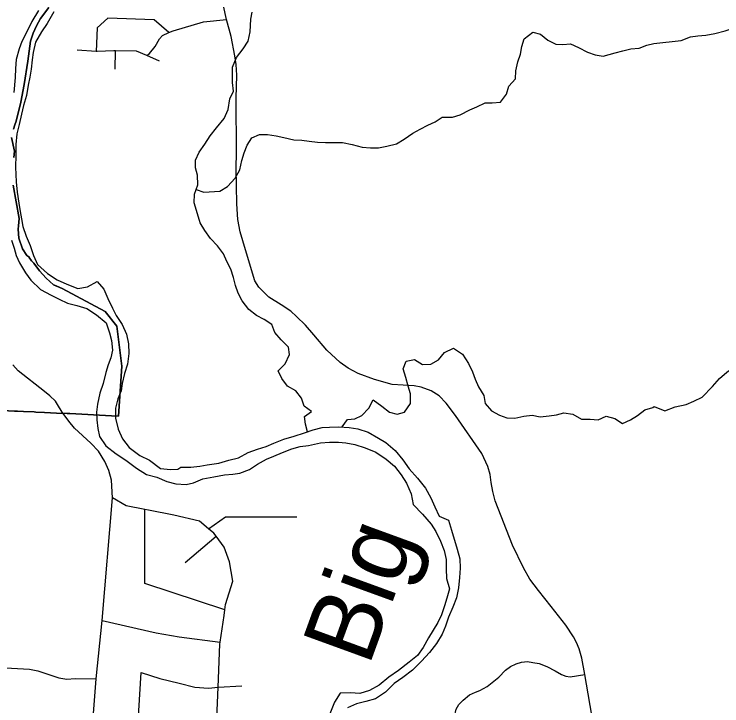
# Model space of a CAD drawing. Extents: x 0 to 34, y 0 to 22.
# Drawn here: x 6.952 to 7.884, y 15.09 to 16 of the extents above; entities that cross this region are included whole.
import ezdxf

# ---------------------------------------------------------------- set-up
doc = ezdxf.new("R2010")
doc.units = 0
for name, color, linetype in [('GM_X_City_Street', 7, 'Continuous'), ('GM_X_Corporation', 7, 'Continuous'), ('GM_X_County_Road', 7, 'Continuous'), ('GM_X_Major_River', 7, 'Continuous'), ('GM_X_Major_River_Text', 7, 'Continuous'), ('GM_X_Minor_Lake', 7, 'Continuous'), ('GM_X_Minor_River', 7, 'Continuous')]:
    doc.layers.add(name, color=color, linetype=linetype)

msp = doc.modelspace()

# ---------------------------------------------------------------- linework, layer by layer
at = {"layer": 'GM_X_City_Street'}
for p, q in [((7.08497, 15.92792), (7.08547, 15.95214)), ((7.17719, 15.27848), (7.2179, 15.31291)), ((7.22068, 15.11423), (7.25195, 15.11592))]:
    msp.add_line(p, q, dxfattribs=at)
for points in [[(7.15596, 15.97631), (7.1365, 15.9931), (7.07538, 15.99512), (7.06123, 15.98249), (7.06015, 15.95124)], [(7.1269, 15.94587), (7.1303, 15.94854), (7.13785, 15.95767), (7.14349, 15.96794), (7.14727, 15.97251), (7.15596, 15.97631), (7.16126, 15.97862), (7.20136, 15.99052), (7.23188, 15.99332)], [(7.14357, 15.93853), (7.1269, 15.94587), (7.11326, 15.95167), (7.08547, 15.95214), (7.08345, 15.95217), (7.06123, 15.95116), (7.06015, 15.95124), (7.03496, 15.95318)], [(7.00904, 15.48646), (7.00648, 15.49066), (6.99904, 15.49765), (6.99197, 15.50353), (6.9571, 15.53091), (6.95032, 15.53886)], [(7.01706, 14.54029), (7.03439, 14.79601), (7.04866, 14.97746), (7.0599, 15.12511), (7.06774, 15.2021), (7.08142, 15.3637), (7.08044, 15.38667), (7.07677, 15.39963), (7.07133, 15.41126), (7.06309, 15.42505), (7.05282, 15.43556), (7.03155, 15.45512), (7.02397, 15.46441), (7.01517, 15.47638), (7.00904, 15.48646)], [(7.21774, 15.0422), (7.22068, 15.11423), (7.22299, 15.17085), (7.2234, 15.17362), (7.22854, 15.20845), (7.22949, 15.21606), (7.23039, 15.22325), (7.24013, 15.25364), (7.23588, 15.27943), (7.22862, 15.29838), (7.2179, 15.31291), (7.21493, 15.31693), (7.20818, 15.3227), (7.19632, 15.33281), (7.16221, 15.34067), (7.12886, 15.34738), (7.12434, 15.34825), (7.09968, 15.35298), (7.08142, 15.3637)], [(7.22949, 15.21606), (7.12426, 15.2506), (7.12434, 15.34825)], [(7.20818, 15.3227), (7.23038, 15.33861), (7.3243, 15.33854)], [(7.06774, 15.2021), (7.13887, 15.18576), (7.16918, 15.18055), (7.2234, 15.17362)], [(7.5378, 15.09161), (7.54324, 15.09715), (7.552, 15.104), (7.55986, 15.10763), (7.5653, 15.10975), (7.57512, 15.11519), (7.58389, 15.12199), (7.59023, 15.12758), (7.5993, 15.13664), (7.60595, 15.14148), (7.6132, 15.14511), (7.62046, 15.14737), (7.62801, 15.14783), (7.63511, 15.14692), (7.64343, 15.14541), (7.65385, 15.14133), (7.66443, 15.13559), (7.67289, 15.13075), (7.67848, 15.12879), (7.68453, 15.12803), (7.70388, 15.13089)], [(6.90876, 15.14136), (6.97202, 15.13778), (6.98301, 15.13591), (7.01069, 15.12652), (7.02129, 15.12465), (7.03227, 15.12583), (7.0599, 15.12511)], [(7.10966, 14.97517), (7.11934, 15.13371), (7.14399, 15.12582), (7.16938, 15.11945), (7.18985, 15.1142), (7.20803, 15.11275), (7.22068, 15.11423)], [(7.53954, 15.02635), (7.53561, 15.03146), (7.53404, 15.04089), (7.53296, 15.05459), (7.53145, 15.06849), (7.5319, 15.07575), (7.53417, 15.08527), (7.5378, 15.09161)]]:
    msp.add_lwpolyline(points, dxfattribs=at)
at = {"layer": 'GM_X_Corporation'}
for points in [[(6.9976, 16.00898), (6.98676, 15.99463), (6.98135, 15.9852), (6.97689, 15.97529), (6.97341, 15.96499), (6.97023, 15.93838), (6.96527, 15.90778), (6.96076, 15.88449), (6.95451, 15.85959), (6.95296, 15.85476), (6.95112, 15.8492)], [(6.95112, 15.8492), (6.95296, 15.85476), (6.95451, 15.85959), (6.96076, 15.88449), (6.96527, 15.90778), (6.97023, 15.93838), (6.97341, 15.96499), (6.97689, 15.97529), (6.98135, 15.9852), (6.98676, 15.99463), (6.9976, 16.00898)], [(6.9484, 15.83781), (6.95234, 15.81982), (6.9514, 15.81153)], [(6.9514, 15.81153), (6.95234, 15.81982), (6.9484, 15.83781)], [(6.95088, 15.77545), (6.95845, 15.73118), (6.95779, 15.7219), (6.95745, 15.71716), (6.95817, 15.70556), (6.96303, 15.6914), (6.96855, 15.68277), (6.97138, 15.6807), (6.97274, 15.6787), (6.97391, 15.67714), (6.97505, 15.67543), (6.97792, 15.67269), (6.98543, 15.66227), (6.99403, 15.65275), (7.00364, 15.64423), (7.0151, 15.63912), (7.07192, 15.60871), (7.08735, 15.58964), (7.09384, 15.53675), (7.08929, 15.47127), (7.08015, 15.47173), (7.02527, 15.47457), (7.02192, 15.47477), (7.00795, 15.47519), (6.99215, 15.47594), (6.98049, 15.4765), (6.97819, 15.47661), (6.96425, 15.47727), (6.95624, 15.47766), (6.95241, 15.47784), (6.93684, 15.4786)], [(6.93684, 15.4786), (6.95241, 15.47784), (6.95624, 15.47766), (6.96425, 15.47727), (6.97819, 15.47661), (6.98049, 15.4765), (6.99215, 15.47594), (7.00795, 15.47519), (7.02192, 15.47477), (7.02527, 15.47457), (7.08015, 15.47173), (7.08929, 15.47127), (7.09384, 15.53675), (7.08735, 15.58964), (7.07192, 15.60871), (7.0151, 15.63912), (7.00755, 15.64257), (7.00364, 15.64423), (6.99403, 15.65275), (6.98543, 15.66227), (6.97792, 15.67269), (6.97505, 15.67543), (6.97391, 15.67714), (6.97274, 15.6787), (6.97138, 15.6807), (6.96855, 15.68277), (6.96303, 15.6914), (6.95817, 15.70556), (6.95745, 15.71716), (6.95779, 15.7219), (6.95845, 15.73118), (6.95088, 15.77545)]]:
    msp.add_lwpolyline(points, dxfattribs=at)
at = {"layer": 'GM_X_County_Road'}
msp.add_lwpolyline([(7.7149, 15.06487), (7.70388, 15.13089), (7.69962, 15.15249), (7.69627, 15.16466), (7.69292, 15.17318), (7.68897, 15.18049), (7.67862, 15.19601), (7.65915, 15.22066), (7.64271, 15.24135), (7.63115, 15.25657), (7.62293, 15.27117), (7.60863, 15.3013), (7.5855, 15.35952), (7.58236, 15.37209), (7.5804, 15.38388), (7.57883, 15.39448), (7.57607, 15.4047), (7.56822, 15.42199), (7.53325, 15.47188), (7.52107, 15.48839), (7.51164, 15.49782), (7.50143, 15.50449), (7.48807, 15.50921), (7.47903, 15.51117), (7.44978, 15.51281), (7.42665, 15.51919), (7.40534, 15.52741), (7.39195, 15.53411), (7.38161, 15.54172), (7.36396, 15.55815), (7.34691, 15.57824), (7.33596, 15.59102), (7.32379, 15.60228), (7.31648, 15.60927), (7.3037, 15.61749), (7.28757, 15.62784), (7.27449, 15.64093), (7.26901, 15.64914), (7.25653, 15.69023), (7.24984, 15.71366), (7.24679, 15.73009), (7.24527, 15.75048), (7.24466, 15.79795), (7.24482, 15.81773), (7.24466, 15.8897), (7.24543, 15.91998), (7.24451, 15.93413), (7.24269, 15.94555), (7.23767, 15.97111), (7.23188, 15.99332), (7.21804, 16.05586)], dxfattribs=at)
at = {"layer": 'GM_X_Major_River'}
for points in [[(6.98395, 16.0053), (6.97515, 15.99091), (6.96864, 15.97727), (6.96212, 15.96439), (6.95866, 15.95491), (6.9548, 15.94088), (6.9536, 15.92873), (6.95316, 15.91696), (6.95155, 15.89723)], [(7.00442, 16.0033), (6.99562, 15.98816), (6.98798, 15.97718), (6.98033, 15.96355), (6.97684, 15.94989), (6.97566, 15.9404), (6.97446, 15.92788), (6.97251, 15.91725), (6.97056, 15.90701), (6.96822, 15.89335), (6.96436, 15.88008), (6.96164, 15.8687), (6.95854, 15.85505), (6.95544, 15.84291), (6.95424, 15.82887), (6.95417, 15.81482), (6.95371, 15.79887), (6.95404, 15.78938), (6.95475, 15.7795), (6.9562, 15.7662), (6.95802, 15.75139), (6.95987, 15.74037), (6.96171, 15.73087), (6.96356, 15.72099), (6.96805, 15.70805), (6.97292, 15.69588), (6.9774, 15.68257), (6.98265, 15.67078), (6.99587, 15.65895), (7.00872, 15.65053), (7.02121, 15.64478), (7.03598, 15.6394), (7.04851, 15.64124), (7.06144, 15.64839), (7.07011, 15.6381), (7.07536, 15.62592), (7.08175, 15.61337), (7.08625, 15.60385), (7.09415, 15.59167), (7.09978, 15.57911), (7.10275, 15.56619), (7.10307, 15.55366), (7.1011, 15.53962), (7.09725, 15.5271), (7.09415, 15.51421), (7.09296, 15.50434), (7.08874, 15.49411), (7.08564, 15.4816), (7.08558, 15.46831), (7.08892, 15.45386), (7.09493, 15.44131), (7.10359, 15.42988), (7.11758, 15.41918), (7.13044, 15.41305), (7.1448, 15.40235), (7.15807, 15.40077), (7.16755, 15.40111)], [(6.94868, 15.70283), (6.95204, 15.69218), (6.95465, 15.68268), (6.95915, 15.67279), (6.96705, 15.65984), (6.97383, 15.65031), (6.98666, 15.63773), (7.00066, 15.63045), (7.01126, 15.62508), (7.02223, 15.61971), (7.03473, 15.61662), (7.04761, 15.61276), (7.06046, 15.60473), (7.0733, 15.59404), (7.07779, 15.58073), (7.0804, 15.57085), (7.08147, 15.55793), (7.07952, 15.54807), (7.07569, 15.53859), (7.0726, 15.52874), (7.06912, 15.51394), (7.06488, 15.50144), (7.06177, 15.48702), (7.06058, 15.4764), (7.06091, 15.46614), (7.06237, 15.45475), (7.0646, 15.44448), (7.07288, 15.43192), (7.08648, 15.4216), (7.09896, 15.41319), (7.11332, 15.4025), (7.12618, 15.39446), (7.13981, 15.3906), (7.15306, 15.38523), (7.1648, 15.38214), (7.17845, 15.38093), (7.18833, 15.38317), (7.20049, 15.38843), (7.21492, 15.39102), (7.22897, 15.39399), (7.23997, 15.3947)], [(7.16755, 15.40111), (7.17174, 15.40412), (7.18464, 15.40406), (7.19678, 15.40515), (7.20627, 15.407), (7.22145, 15.40921), (7.23475, 15.41333), (7.24766, 15.4163), (7.26021, 15.42346), (7.27237, 15.42758), (7.28415, 15.43132), (7.29403, 15.43545), (7.30733, 15.44071), (7.32101, 15.44482), (7.33431, 15.44932), (7.3457, 15.45306), (7.35786, 15.45604), (7.36734, 15.45676), (7.37986, 15.45708), (7.39313, 15.45626), (7.4045, 15.45431), (7.41814, 15.45007), (7.43175, 15.44203), (7.44158, 15.43629), (7.45405, 15.42598), (7.46385, 15.41379), (7.47252, 15.4016), (7.48308, 15.3894), (7.49363, 15.37644), (7.50078, 15.3635), (7.50603, 15.35171), (7.51166, 15.33953), (7.52415, 15.33416), (7.52826, 15.32085), (7.53572, 15.29576), (7.53907, 15.28322), (7.53939, 15.27107), (7.53857, 15.25854), (7.53736, 15.24526), (7.53464, 15.23198), (7.53003, 15.21947), (7.52427, 15.20621), (7.52004, 15.19446), (7.51582, 15.18423), (7.50817, 15.17174), (7.49901, 15.16001), (7.48871, 15.14829), (7.47652, 15.13658), (7.46395, 15.12714), (7.45254, 15.11922), (7.4411, 15.1075), (7.42778, 15.09883), (7.41525, 15.09547), (7.40309, 15.09211), (7.39093, 15.08723)], [(7.23997, 15.3947), (7.24946, 15.39617), (7.262, 15.40105), (7.27265, 15.40784), (7.28445, 15.41462), (7.29395, 15.41837), (7.30535, 15.42325), (7.31789, 15.42813), (7.32853, 15.43112), (7.33953, 15.43259), (7.35548, 15.43593), (7.36724, 15.43701), (7.37938, 15.43696), (7.38886, 15.43616), (7.40061, 15.43382), (7.41424, 15.42959), (7.42825, 15.42382), (7.44186, 15.41465), (7.45319, 15.4051), (7.46186, 15.39367), (7.46901, 15.38301), (7.47501, 15.36894), (7.47759, 15.35488), (7.49005, 15.34191), (7.50136, 15.32895), (7.50739, 15.31943), (7.51339, 15.30649), (7.51826, 15.29432), (7.52086, 15.28216), (7.52118, 15.27001), (7.52149, 15.25748), (7.5256, 15.24379), (7.52212, 15.23128), (7.51866, 15.22142), (7.51481, 15.20929), (7.51021, 15.19944), (7.50409, 15.18922), (7.49759, 15.17938), (7.4907, 15.1665), (7.48344, 15.15591), (7.4724, 15.14722), (7.45831, 15.13628), (7.44537, 15.12723), (7.4328, 15.11703), (7.42025, 15.10988), (7.40733, 15.10576), (7.3952, 15.10695), (7.38154, 15.10626), (7.3739, 15.09452), (7.36622, 15.07482)]]:
    msp.add_lwpolyline(points, dxfattribs=at)
at = {"layer": 'GM_X_Minor_Lake'}
for points in [[(7.79469, 15.96174), (7.83058, 15.96592), (7.84276, 15.97078), (7.85263, 15.97186), (7.86288, 15.97294), (7.87504, 15.97515), (7.88873, 15.97848), (7.90014, 15.98221), (7.91485, 15.98607)], [(7.79488, 15.4836), (7.8089, 15.47797), (7.82259, 15.4832), (7.83704, 15.48653), (7.84731, 15.49064), (7.85835, 15.49627), (7.87172, 15.51023), (7.88128, 15.5208), (7.89082, 15.5291), (7.90378, 15.53813), (7.91638, 15.54982), (7.92139, 15.56307), (7.92411, 15.57255)]]:
    msp.add_lwpolyline(points, dxfattribs=at)
at = {"layer": 'GM_X_Minor_River'}
for points in [[(7.33841, 15.45066), (7.33569, 15.46055), (7.33426, 15.47044), (7.3438, 15.47719), (7.33401, 15.48412), (7.33069, 15.49478), (7.3232, 15.50434), (7.31227, 15.51052), (7.3044, 15.52085), (7.29956, 15.53077), (7.30912, 15.53979), (7.31454, 15.55227), (7.31349, 15.56178), (7.30373, 15.57174), (7.29548, 15.58132), (7.2914, 15.59199), (7.28123, 15.59816), (7.27104, 15.60357), (7.26126, 15.61164), (7.25227, 15.62273), (7.24706, 15.63304), (7.24373, 15.64294), (7.2408, 15.6536), (7.23749, 15.66465), (7.23227, 15.67457), (7.22782, 15.68487), (7.21996, 15.69557), (7.21057, 15.70516), (7.20308, 15.71548), (7.19711, 15.72579), (7.19343, 15.7376), (7.18901, 15.75207), (7.1895, 15.76346), (7.19378, 15.77557), (7.19352, 15.78849), (7.19095, 15.79801), (7.19066, 15.80826), (7.19569, 15.81885), (7.20298, 15.82941), (7.21029, 15.84036), (7.21834, 15.85092), (7.22869, 15.86297), (7.23372, 15.87508), (7.23612, 15.88873), (7.24076, 15.89894), (7.23973, 15.91034), (7.23944, 15.92022), (7.23954, 15.93048), (7.24496, 15.94334), (7.25378, 15.95465), (7.26032, 15.96484), (7.26308, 15.97735), (7.26361, 15.99368), (7.26559, 16.00315)], [(7.19159, 15.76939), (7.20165, 15.766), (7.22289, 15.76732), (7.23318, 15.77368), (7.24313, 15.7846), (7.2493, 15.79556), (7.25206, 15.80769), (7.25518, 15.81791), (7.25906, 15.82775), (7.26522, 15.83757), (7.27511, 15.84203), (7.28572, 15.84193), (7.29708, 15.84031), (7.30729, 15.83793), (7.32053, 15.83477), (7.33076, 15.83467), (7.3406, 15.83306), (7.35158, 15.83182), (7.36219, 15.83134), (7.37356, 15.83123), (7.38455, 15.83151), (7.39741, 15.82873), (7.41026, 15.82519), (7.42125, 15.82433), (7.43186, 15.82461), (7.44287, 15.82641), (7.45579, 15.8297), (7.4657, 15.83569), (7.47714, 15.84356), (7.48666, 15.84878), (7.49694, 15.85438), (7.50646, 15.85847), (7.51599, 15.86484), (7.52926, 15.86472), (7.53952, 15.86804), (7.55208, 15.87438), (7.5616, 15.87847), (7.57226, 15.88368), (7.58173, 15.88359), (7.59273, 15.88463), (7.60041, 15.89519), (7.60353, 15.90542), (7.61234, 15.91521), (7.61282, 15.92584), (7.61558, 15.93759), (7.61908, 15.94781), (7.62069, 15.95805), (7.62381, 15.96789), (7.63527, 15.9769), (7.6451, 15.97415), (7.65488, 15.96608), (7.66544, 15.96105), (7.67491, 15.96058), (7.68477, 15.96125), (7.69534, 15.95659), (7.70741, 15.9504), (7.71724, 15.94689), (7.72783, 15.94489), (7.74379, 15.9493), (7.75367, 15.95224), (7.76431, 15.9548), (7.77531, 15.95584), (7.78557, 15.95954), (7.79469, 15.96174)], [(7.384, 15.45682), (7.39108, 15.46649), (7.40056, 15.46754), (7.41008, 15.47201), (7.41926, 15.4818), (7.42505, 15.49276), (7.43634, 15.4843), (7.4465, 15.47623), (7.45672, 15.47385), (7.46621, 15.47642), (7.47428, 15.48774), (7.47401, 15.50065), (7.47107, 15.51055), (7.46814, 15.52197), (7.46446, 15.5334), (7.46834, 15.54362), (7.47935, 15.54579), (7.4899, 15.53924), (7.5009, 15.53951), (7.5108, 15.54512), (7.51885, 15.55492), (7.53065, 15.5605), (7.54271, 15.5528), (7.55056, 15.54057), (7.55576, 15.52951), (7.55946, 15.5196), (7.56354, 15.50969), (7.57064, 15.49823), (7.57244, 15.48758), (7.58069, 15.47801), (7.59125, 15.47259), (7.60107, 15.46908), (7.61168, 15.4686), (7.62345, 15.47115), (7.63445, 15.47219), (7.64467, 15.47019), (7.65681, 15.4716), (7.6663, 15.47265), (7.67618, 15.47559), (7.68791, 15.47359), (7.69922, 15.46702), (7.71059, 15.4673), (7.72119, 15.46606), (7.73185, 15.4709), (7.74319, 15.46813), (7.75337, 15.46158), (7.76365, 15.46642), (7.77317, 15.47203), (7.78272, 15.47953), (7.79335, 15.48247), (7.79488, 15.4836)]]:
    msp.add_lwpolyline(points, dxfattribs=at)

# ---------------------------------------------------------------- texts
at = {"layer": 'GM_X_Major_River_Text'}
msp.add_text('Big', height=0.094697, rotation=69.99994, dxfattribs=at).set_placement((7.41904, 15.14027))

doc.saveas('drawing.dxf')
